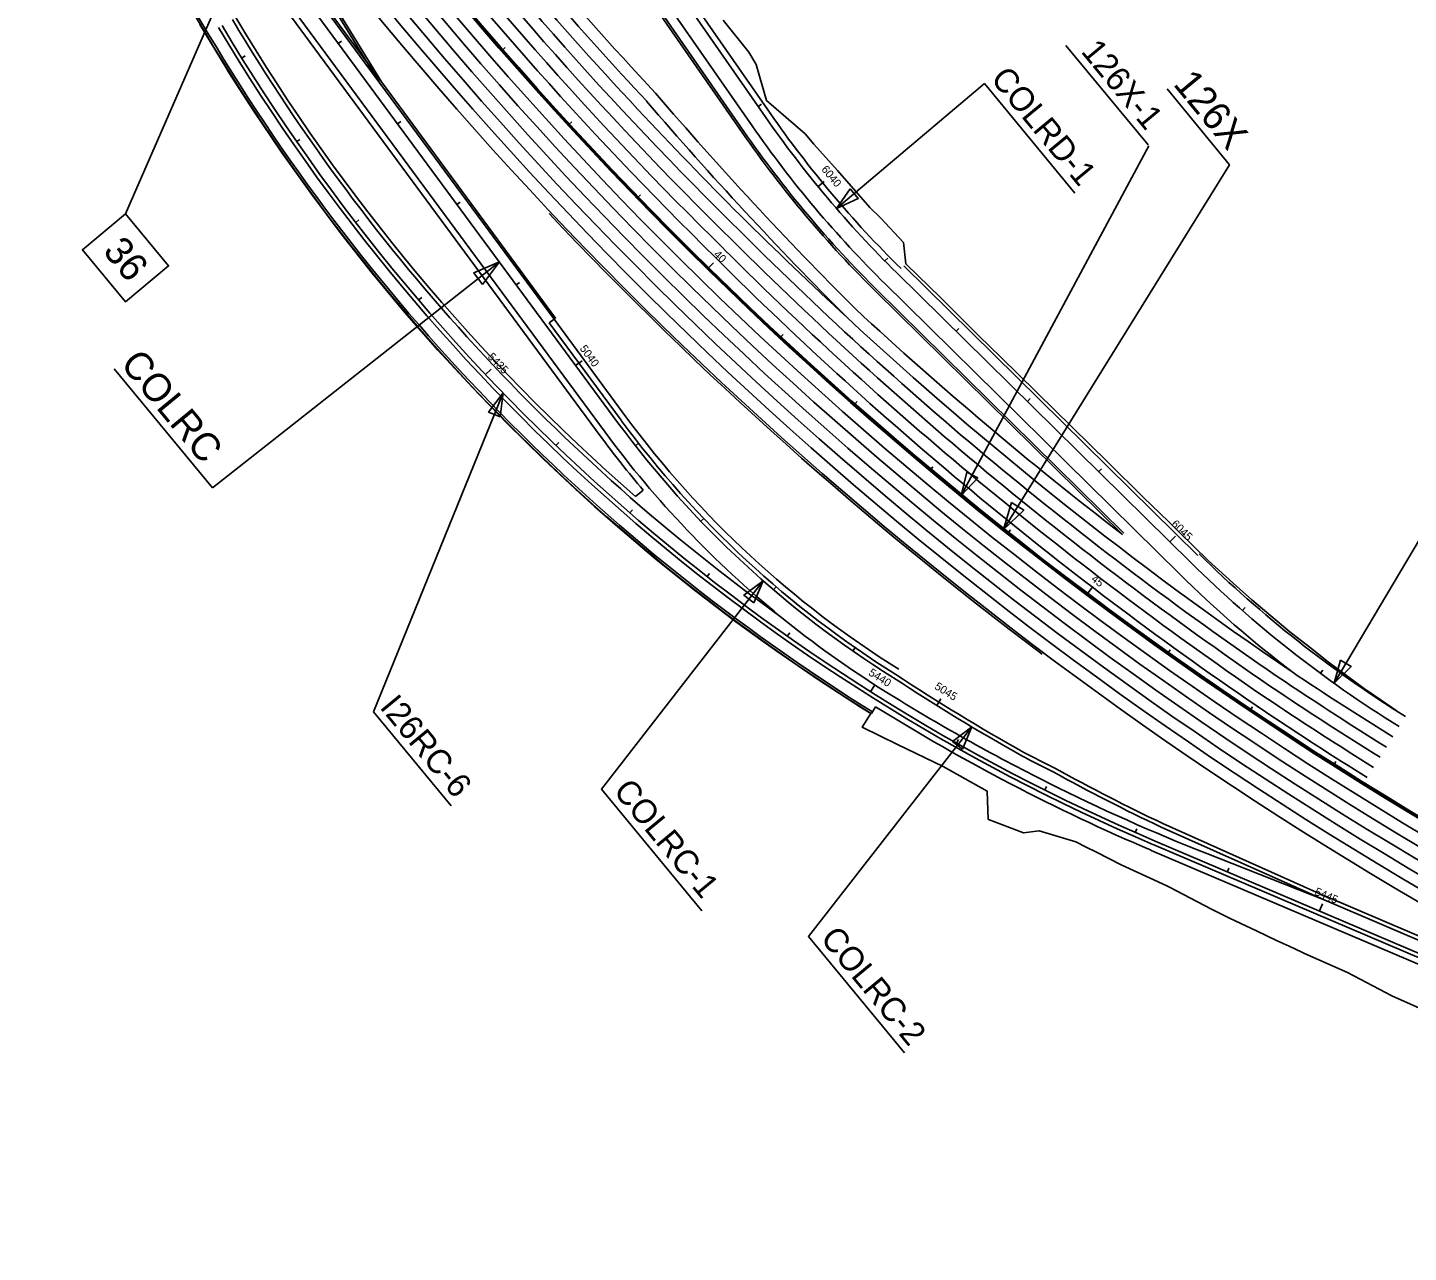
# Model space of a CAD drawing. Extents: x 1944333 to 1975203, y 788957 to 827579.
# Drawn here: x 1970942 to 1972322, y 794492 to 795717 of the extents above; entities that cross this region are included whole.
import ezdxf

# ---------------------------------------------------------------- set-up
doc = ezdxf.new("R2010")
doc.units = 0
for name, color, linetype in [('RD_HC_CL_Rel', 7, 'Continuous'), ('RD_HC_Data_Tic_Rel', 7, 'Continuous'), ('RD_HC_TX_Rel_Sta50', 7, 'Continuous'), ('RD_PD_ALT1_LnLine', 7, 'Continuous'), ('RD_PD_ALT1_TrvlWay', 7, 'Continuous'), ('RD_PD_CstnLmt', 7, 'Continuous'), ('RD_PD_GR', 7, 'Continuous'), ('RD_PD_MedBWall', 7, 'Continuous'), ('RD_PD_PaveShd', 7, 'Continuous'), ('RD_PD_WallFill', 7, 'Continuous'), ('RD_TX_RoadID', 7, 'Continuous')]:
    doc.layers.add(name, color=color, linetype=linetype)

msp = doc.modelspace()

# ---------------------------------------------------------------- linework, layer by layer
at = {"layer": 'RD_HC_CL_Rel'}
for p, q in [((1971382, 796056.4), (1971679.3, 795627.9)), ((1971135.3, 795860.1), (1971532.1, 795321.9)), ((1971810.9, 795471.6), (1972104.6, 795182.1)), ((1972069.1, 794903.6), (1973025.7, 794496.1))]:
    msp.add_line(p, q, dxfattribs=at)
for centre, radius, start, end in [((1974296, 798203.9), 3819.7, 216.3977, 243.9112), ((1972851.5, 796739.9), 1996, 210.7638, 246.9227), ((1972583, 796255.1), 1100, 214.7587, 225.416), ((1972337, 795915.3), 1000, 216.3977, 238.0375), ((1972947, 796036.8), 1200, 225.416, 238.0979), ((1972897.2, 796713.8), 1974.7, 236.5123, 240.8705)]:
    msp.add_arc(centre, radius, start, end, dxfattribs=at)
at = {"layer": 'RD_HC_Data_Tic_Rel'}
for p, q in [((1971252.5, 795701.1), (1971255.7, 795703.5)), ((1971416.3, 795694.4), (1971419.4, 795697)), ((1971156.1, 795686.5), (1971159.5, 795688.7)), ((1971672.3, 795638.1), (1971675.6, 795640.3)), ((1971311.8, 795620.6), (1971315, 795623)), ((1971483, 795619.9), (1971486, 795622.6)), ((1971211, 795603), (1971214.3, 795605.2)), ((1971732.1, 795558), (1971738.3, 795563)), ((1971371.2, 795540.1), (1971374.4, 795542.5)), ((1971551.6, 795547.1), (1971554.5, 795549.9)), ((1971270, 795522.2), (1971273.1, 795524.7)), ((1971798.9, 795483.6), (1971801.8, 795486.4)), ((1971622.1, 795476.2), (1971627.7, 795481.9)), ((1971430.5, 795459.6), (1971433.7, 795462)), ((1971332.9, 795444.6), (1971336, 795447.1)), ((1971870.1, 795413.3), (1971872.9, 795416.2)), ((1971694.4, 795407.1), (1971697.2, 795410.1)), ((1971399.7, 795370.1), (1971405.5, 795375.6)), ((1971489.8, 795379.1), (1971496.3, 795383.9)), ((1971941.3, 795343.1), (1971944.1, 795346)), ((1971768.5, 795340), (1971771.2, 795343)), ((1971470.1, 795299.1), (1971472.9, 795302)), ((1971549.5, 795298.9), (1971552.7, 795301.4)), ((1971844.4, 795274.8), (1971846.9, 795277.9)), ((1972012.5, 795272.9), (1972015.3, 795275.8)), ((1971544, 795231.8), (1971546.6, 795234.8)), ((1971615, 795223.4), (1971617.9, 795226.1)), ((1971921.9, 795211.6), (1971924.4, 795214.8)), ((1972083.7, 795202.7), (1972089.3, 795208.4)), ((1971621.2, 795168.2), (1971623.7, 795171.3)), ((1971687.7, 795154.7), (1971690.3, 795157.8)), ((1972001, 795150.5), (1972005.8, 795156.9)), ((1972156.4, 795134.1), (1972159, 795137.1)), ((1971701.4, 795108.5), (1971703.8, 795111.8)), ((1971766.8, 795093.7), (1971769.1, 795097)), ((1972081.8, 795091.5), (1972084.1, 795094.7)), ((1972234.3, 795071.4), (1972236.6, 795074.6)), ((1971784.6, 795053), (1971788.9, 795059.8)), ((1971850.7, 795039.2), (1971854.9, 795046)), ((1972164, 795034.6), (1972166.2, 795037.9)), ((1971870.4, 795001.7), (1971872.4, 795005.2)), ((1972247.7, 794979.9), (1972249.8, 794983.2)), ((1971958.7, 794954.7), (1971960.5, 794958.3)), ((1972049.2, 794912.3), (1972050.8, 794915.9)), ((1972141.2, 794873), (1972142.7, 794876.6)), ((1972233.2, 794833.8), (1972236.3, 794841.1))]:
    msp.add_line(p, q, dxfattribs=at)
at = {"layer": 'RD_PD_ALT1_LnLine'}
msp.add_line((1972120.6, 794891.1), (1972237.9, 794844.8), dxfattribs=at)
for centre, radius, start, end in [((1974296, 798203.9), 3758.7, 217.2297, 223.1115), ((1974296, 798203.9), 3782.7, 217.2379, 225.5447), ((1974296, 798203.9), 3770.7, 217.2585, 225.5447), ((1974296, 798203.9), 3794.7, 217.2419, 225.5447), ((1974296, 798203.9), 3844.7, 217.2585, 243.9112), ((1974296, 798203.9), 3868.7, 217.2663, 243.9112), ((1974296, 798203.9), 3856.7, 217.2624, 243.9112), ((1974306.4, 798193.7), 3759.3, 222.8888, 227.3888), ((1974321.2, 798184.1), 3774.4, 225.0605, 235.7907), ((1974321.1, 798183.9), 3786.1, 225.0617, 235.7926), ((1974320.9, 798183.7), 3797.9, 225.0628, 235.7946), ((1972337, 795915.3), 1016, 230.7653, 238.0375), ((1974296, 798203.9), 3764.7, 236.2764, 238.0979), ((1974296, 798203.9), 3776.7, 236.2764, 238.0979), ((1972851.5, 796739.9), 1988, 238.0375, 243.4287), ((1974296, 798203.9), 3800.7, 236.2764, 238.0979), ((1974296, 798203.9), 3788.7, 236.2764, 238.0979), ((1972851.5, 796739.9), 1988, 243.4287, 248.4286)]:
    msp.add_arc(centre, radius, start, end, dxfattribs=at)
at = {"layer": 'RD_PD_ALT1_TrvlWay'}
for p, q in [((1971666.2, 795618.8), (1971392.7, 796013)), ((1971679.3, 795627.9), (1971431.1, 795985.6)), ((1971122.4, 795850.6), (1971519.2, 795312.4)), ((1971167.4, 795816.5), (1971532.1, 795321.9)), ((1971810.9, 795471.6), (1972104.6, 795182.1)), ((1971797.9, 795462), (1972093.4, 795170.7)), ((1972075.1, 794917.6), (1972237.9, 794844.8)), ((1972067.6, 794900), (1973024, 794492.5)), ((1972237.9, 794844.8), (1972960.6, 794536.9))]:
    msp.add_line(p, q, dxfattribs=at)
for centre, radius, start, end in [((1974296, 798203.9), 3806.7, 217.2459, 225.5447), ((1974296, 798203.9), 3832.7, 217.2545, 243.9112), ((1974296, 798203.9), 3746.7, 218.6115, 223.1115), ((1974296, 798203.9), 3880.7, 217.2701, 243.9112), ((1972851.5, 796739.9), 1984, 210.7638, 234.3208), ((1972851.5, 796739.9), 2000, 210.7638, 246.9227), ((1974415.1, 798086.3), 3757, 220.559, 225.059), ((1972583, 796255.1), 1100, 214.7587, 225.416), ((1972583, 796255.1), 1116, 214.7587, 225.416), ((1974320.7, 798183.5), 3809.6, 225.0639, 235.7965), ((1974322.1, 798185.2), 3763.7, 227.1254, 235.7873), ((1972337, 795915.3), 1000, 216.3977, 238.0375), ((1972337, 795915.3), 1016, 216.3977, 230.7653), ((1972947, 796036.8), 1200, 225.416, 238.0979), ((1972947, 796036.8), 1216, 225.416, 232.4504), ((1972897.2, 796713.8), 1974.7, 236.5123, 240.8705), ((1974296, 798203.9), 3812.7, 236.2764, 238.0979), ((1972851.5, 796739.9), 1976, 242.3957, 243.4287), ((1972923.3, 796706.7), 1980, 241.1416, 244.6356)]:
    msp.add_arc(centre, radius, start, end, dxfattribs=at)
at = {"layer": 'RD_PD_CstnLmt'}
for points in [[(1971114.3, 795719.9), (1971140.4, 795676.8), (1971143.3, 795672), (1971143.3, 795672), (1971167.6, 795634.3), (1971195.8, 795592.4), (1971225, 795551.3), (1971255.3, 795510.9), (1971286.6, 795471.3), (1971318.9, 795432.5), (1971352.1, 795394.6), (1971386.3, 795357.4), (1971421.4, 795321.2), (1971457.3, 795285.8), (1971479.4, 795265), (1971494.2, 795251.3), (1971494.2, 795251.3), (1971508.6, 795238.3), (1971508.6, 795238.3), (1971516.7, 795231.1), (1971526.9, 795222.1), (1971526.9, 795222.1), (1971527, 795222.1), (1971531.9, 795217.8), (1971531.9, 795217.8), (1971570.4, 795185.2), (1971609.8, 795153.6), (1971649.9, 795123), (1971675, 795104.7), (1971690.8, 795093.4), (1971732.4, 795064.9), (1971774.7, 795037.4), (1971784.7, 795031.1)], [(1972310, 795034.3), (1972305.5, 795037.3), (1972282.2, 795053.1), (1972278.4, 795055.8), (1972242.4, 795082.4), (1972224.3, 795096.7), (1972224.3, 795096.7), (1972203.6, 795113), (1972165.7, 795144.7), (1972150.2, 795158.5), (1972128.9, 795177.7), (1972122.1, 795184.3), (1972093.2, 795212.4), (1972082.7, 795222.7), (1972065.3, 795239.6), (1972057.4, 795247.3), (1972021.8, 795282.4), (1971986.2, 795317.5), (1971950.5, 795352.5), (1971914.8, 795387.5), (1971893.3, 795408.6), (1971879.2, 795422.6), (1971854.1, 795447.3), (1971843.5, 795457.6), (1971819.8, 795480.7), (1971817.6, 795502), (1971794.5, 795526.6), (1971794.5, 795526.6), (1971783.8, 795537.2), (1971751.5, 795573.9), (1971727.9, 795600.3), (1971727.9, 795600.3), (1971719.1, 795610.6), (1971680.7, 795643.9), (1971670.4, 795680), (1971663, 795692.5), (1971637.4, 795724.2)], [(1971784.7, 795031.1), (1971776.2, 795017.5), (1971811.4, 795000.3), (1971857.2, 794978.3), (1971901.1, 794953.6), (1971902.3, 794925.3), (1971902.5, 794925.1), (1971902.6, 794925.1), (1971937.5, 794911.9), (1971953, 794913.8), (1971989.6, 794902.8), (1972000.2, 794897.7), (1972010.3, 794892.5), (1972010.3, 794892.5), (1972035, 794880), (1972080.8, 794858.9), (1972083.3, 794857.6), (1972125.2, 794835.5), (1972142.8, 794827), (1972154.8, 794821.3), (1972170.4, 794814.1), (1972190.9, 794804), (1972203.1, 794798.6), (1972215.6, 794792.6), (1972218.2, 794791.4), (1972261.3, 794772.2), (1972305.7, 794748.9), (1972351.4, 794728.5)]]:
    msp.add_lwpolyline(points, dxfattribs=at)
at = {"layer": 'RD_PD_GR'}
msp.add_line((1971468.2, 795425.3), (1971540.1, 795327.8), dxfattribs=at)
for centre, radius, start, end in [((1974296, 798203.9), 3894.7, 223.3358, 233.0708), ((1972337, 795915.3), 990, 216.3977, 238.0375)]:
    msp.add_arc(centre, radius, start, end, dxfattribs=at)
at = {"layer": 'RD_PD_MedBWall'}
for p, q in [((1971177.4, 795819.9), (1971294.1, 795661.5)), ((1971179, 795821), (1971295.7, 795662.7))]:
    msp.add_line(p, q, dxfattribs=at)
for radius, start in [(3820.7, 217.2581), (3818.7, 217.2574)]:
    msp.add_arc((1974296, 798203.9), radius, start, 243.9112, dxfattribs=at)
at = {"layer": 'RD_PD_PaveShd'}
for p, q in [((1971008.7, 795994.7), (1971514.4, 795308.8)), ((1971684.2, 795631.4), (1971591.7, 795764.7)), ((1971817.9, 795478.8), (1972111.6, 795189.3)), ((1971468.2, 795425.3), (1971463.4, 795421.8)), ((1971463.4, 795421.8), (1971535.3, 795324.3)), ((1971549.6, 795248.1), (1971557.3, 795254.6)), ((1971789.6, 795038), (1971785.4, 795031.2)), ((1972076.8, 794921.2), (1972239.5, 794848.4)), ((1972065.2, 794894.4), (1972916.4, 794531.8)), ((1972239.4, 794848.5), (1972517.7, 794729.9))]:
    msp.add_line(p, q, dxfattribs=at)
for centre, radius, start, end in [((1974296, 798203.9), 3734.7, 217.2214, 223.1156), ((1974296, 798203.9), 3892.7, 217.274, 242.8933), ((1972851.5, 796739.9), 1980, 210.7638, 228.8892), ((1974415.1, 798086.3), 3745, 220.5549, 225.0557), ((1972583, 796255.1), 1094, 214.7587, 225.416), ((1974322.1, 798185.2), 3751.7, 227.1287, 232.4627), ((1972337, 795915.3), 996, 216.3977, 238.0375), ((1972337, 795915.3), 1022, 216.3977, 220.277), ((1972947, 796036.8), 1188, 225.416, 238.0979), ((1972897.2, 796713.8), 1970.7, 236.5123, 240.8689), ((1972851.5, 796739.9), 2006, 238.0375, 246.9227), ((1972851.5, 796739.9), 1972, 242.3973, 243.431), ((1972923.3, 796706.7), 1976, 241.1393, 244.6343)]:
    msp.add_arc(centre, radius, start, end, dxfattribs=at)
at = {"layer": 'RD_PD_WallFill'}
for p, q in [((1970942.1, 796010.2), (1971120.9, 795709.7)), ((1970943.8, 796011.3), (1971122.6, 795710.8)), ((1971656.3, 795612), (1971419, 795954)), ((1971420.6, 795955.2), (1971658, 795613.1)), ((1971191, 795829.4), (1971294.1, 795661.5)), ((1971295.7, 795662.7), (1971192.6, 795830.6)), ((1971294.1, 795661.5), (1971468.2, 795425.3)), ((1971295.7, 795662.7), (1971469.8, 795426.5)), ((1971789.5, 795453.4), (1972036.3, 795210.2)), ((1971790.9, 795454.8), (1972037.7, 795211.6)), ((1971469.8, 795426.5), (1971468.2, 795425.3))]:
    msp.add_line(p, q, dxfattribs=at)
for centre, radius, start, end in [((1972851.5, 796739.9), 2014, 210.7638, 238.0375), ((1972851.5, 796739.9), 2012, 210.7638, 238.0375), ((1972583, 796255.1), 1128, 214.7587, 225.416), ((1972583, 796255.1), 1126, 214.7587, 225.416)]:
    msp.add_arc(centre, radius, start, end, dxfattribs=at)
at = {"layer": 'RD_TX_RoadID'}
for p, q in [((1972061.9, 795599.8), (1971979.9, 795699.1)), ((1971988.8, 795551.5), (1971898.4, 795661)), ((1972143.4, 795579.8), (1972080.9, 795655.6)), ((1971126.8, 795256.9), (1971028.5, 795375.8)), ((1971365.4, 794938.9), (1971287.8, 795032.9)), ((1971616, 794834.1), (1971515.6, 794955.7)), ((1971818.6, 794692), (1971722.5, 794808.3))]:
    msp.add_line(p, q, dxfattribs=at)
for points in [[(1971040, 795530.6), (1971173.5, 795837.3)], [(1971898.4, 795661), (1971750.6, 795536)], [(1972062.6, 795598.8), (1971875.3, 795249.2)], [(1972143.4, 795579.8), (1971917.3, 795215.3)], [(1971126.8, 795256.9), (1971413.6, 795482.6)], [(1971287.8, 795032.9), (1971417.3, 795351.7)], [(1972373.3, 795272.6), (1972247.9, 795061.4)], [(1971515.6, 794955.7), (1971677.1, 795163.9)], [(1971722.5, 794808.3), (1971885.7, 795017.8)]]:
    msp.add_lwpolyline(points, dxfattribs=at)
for points in [[(1971764.3, 795555.7), (1971750.6, 795536), (1971772.3, 795546.2)], [(1971040, 795530.6), (1971083, 795478.6), (1971039.8, 795442.9), (1970996.8, 795494.9)], [(1971396.8, 795460.2), (1971413.6, 795482.6), (1971387.9, 795471.6)], [(1971414.3, 795327.9), (1971417.3, 795351.7), (1971402.8, 795332.6)], [(1971880.8, 795272.5), (1971875.3, 795249.2), (1971891.8, 795266.7)], [(1971925.4, 795242.1), (1971917.3, 795215.3), (1971937.7, 795234.5)], [(1971667.8, 795141.8), (1971677.1, 795163.9), (1971658, 795149.4)], [(1972254.4, 795084.5), (1972247.9, 795061.4), (1972265.1, 795078.2)], [(1971876.4, 794995.7), (1971885.7, 795017.8), (1971866.6, 795003.3)]]:
    msp.add_lwpolyline(points, close=True, dxfattribs=at)

# ---------------------------------------------------------------- texts
at = {"layer": 'RD_HC_TX_Rel_Sta50'}
for s, rotation, p in [('6040', 309.3258, (1971734.9, 795575)), ('40', 315.5714, (1971627.2, 795489.4)), ('5435', 313.335, (1971401.4, 795387.3)), ('5040', 306.3977, (1971493.5, 795396)), ('6045', 315.416, (1972084.7, 795220)), ('45', 323.0714, (1972004.4, 795164.3)), ('5440', 327.6876, (1971781.9, 795070.1)), ('5045', 327.9969, (1971847.9, 795056.3)), ('5445', 336.9227, (1972227.8, 794850.2))]:
    msp.add_text(s, height=8, rotation=rotation, dxfattribs=at).set_placement(p)
at = {"layer": 'RD_TX_RoadID'}
for s, height, p in [('126X-1', 24, (1971994.2, 795692.7)), ('COLRD-1', 24, (1971903.8, 795665.4)), ('126X ', 28, (1972086.3, 795660.1)), ('36', 28, (1971016.5, 795493)), ('COLRC  ', 28, (1971033.9, 795380.3)), ('I26RC-6', 24, (1971293.2, 795037.3)), (' COLRC-1 ', 24, (1971521, 794960.2)), (' COLRC-2', 24, (1971727.9, 794812.8))]:
    msp.add_text(s, height=height, rotation=309.5517, dxfattribs=at).set_placement(p)

doc.saveas('drawing.dxf')
